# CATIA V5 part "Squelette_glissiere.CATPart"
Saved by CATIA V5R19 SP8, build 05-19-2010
Part number: Squelette 'glissière'
Publications: "Droite.1", "Droite.2", "Droite.3", "Droite.4", "Droite.5", "Droite.6", "Droite.7", "Droite.8", "Plan.3", "Plan.5", "Droite.9", "Droite.10", "Plan.4", "Plan.6"
Bounding box of the stored display mesh (mm): x -39.5 to 0, y -30 to 30, z -16.5 to 16.5
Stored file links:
  C:\Users\ThinkMotion\Desktop\EU_thinkMotion\iao\IAO_MMS_Groupe3\ecartoux\projet_IAO_ecartoux\projet_IAO_ecartoux\griffe_d'une_camera_ecartoux\Squelette_glissiere.CATPart
  C:\Users\ThinkMotion\Desktop\EU_thinkMotion\iao\IAO_MMS_Groupe3\ecartoux\projet_IAO_ecartoux\projet_IAO_ecartoux\griffe_d'une_camera_ecartoux\Squelette.CATProduct
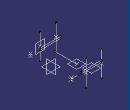
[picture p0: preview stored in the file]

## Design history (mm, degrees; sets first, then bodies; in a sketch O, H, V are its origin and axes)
Set1
  Point1: linked copy from another document
  Plane1: linked copy from another document
  Point2 to Point5: linked copy from another document
  Plane2: linked copy from another document
  Point6 to Point8: linked copy from another document
  Plane3: linked copy from another document
  Point9: linked copy from another document
  Point10: linked copy from another document
Set2 "Set géométrique"
  Line1: type PtDir, RefPoint Point1, Direction Plane1, Start -16.5, End 16.5
  Line2: type PtDir, RefPoint Point2, Direction Plane1, Start -16.5, End 16.5
  Line3: type PtDir, RefPoint Point3, Direction Plane1, Start -16.5, End 16.5
  Line4: type PtDir, RefPoint Point4, Direction Plane1, Start -16.5, End 16.5
  Line5: type PtDir, RefPoint Point5, Direction Plane2, Start 13.5, End 39.5
  Line6: type PtDir, RefPoint Point6, Direction Plane2, Start 13.5, End 39.5
  Line7: type PtDir, RefPoint Point7, Direction Plane2, Start 13.5, End 39.5
  Line8: type PtDir, RefPoint Point8, Direction Plane2, Start 13.5, End 39.5
  Plane4 "Plan.3": type Offset, RefPlane Plane3, Offset 0
  Plane5 "Plan.5": type 2Lines, Element1 Line8, Element2 Line5
  Line9: type PtDir, RefPoint Point9, Direction Plane4, Start -29, End 2.795
  Line10: type PtDir, RefPoint Point10, Direction Plane2, Start 0, End 10
  Plane6 "Plan.4": type OffsetPt, RefPlane Plane3, RefPoint Point1
  Plane7 "Plan.6": type OffsetPt, RefPlane Plane1, RefPoint Point9
Body1 (main body)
